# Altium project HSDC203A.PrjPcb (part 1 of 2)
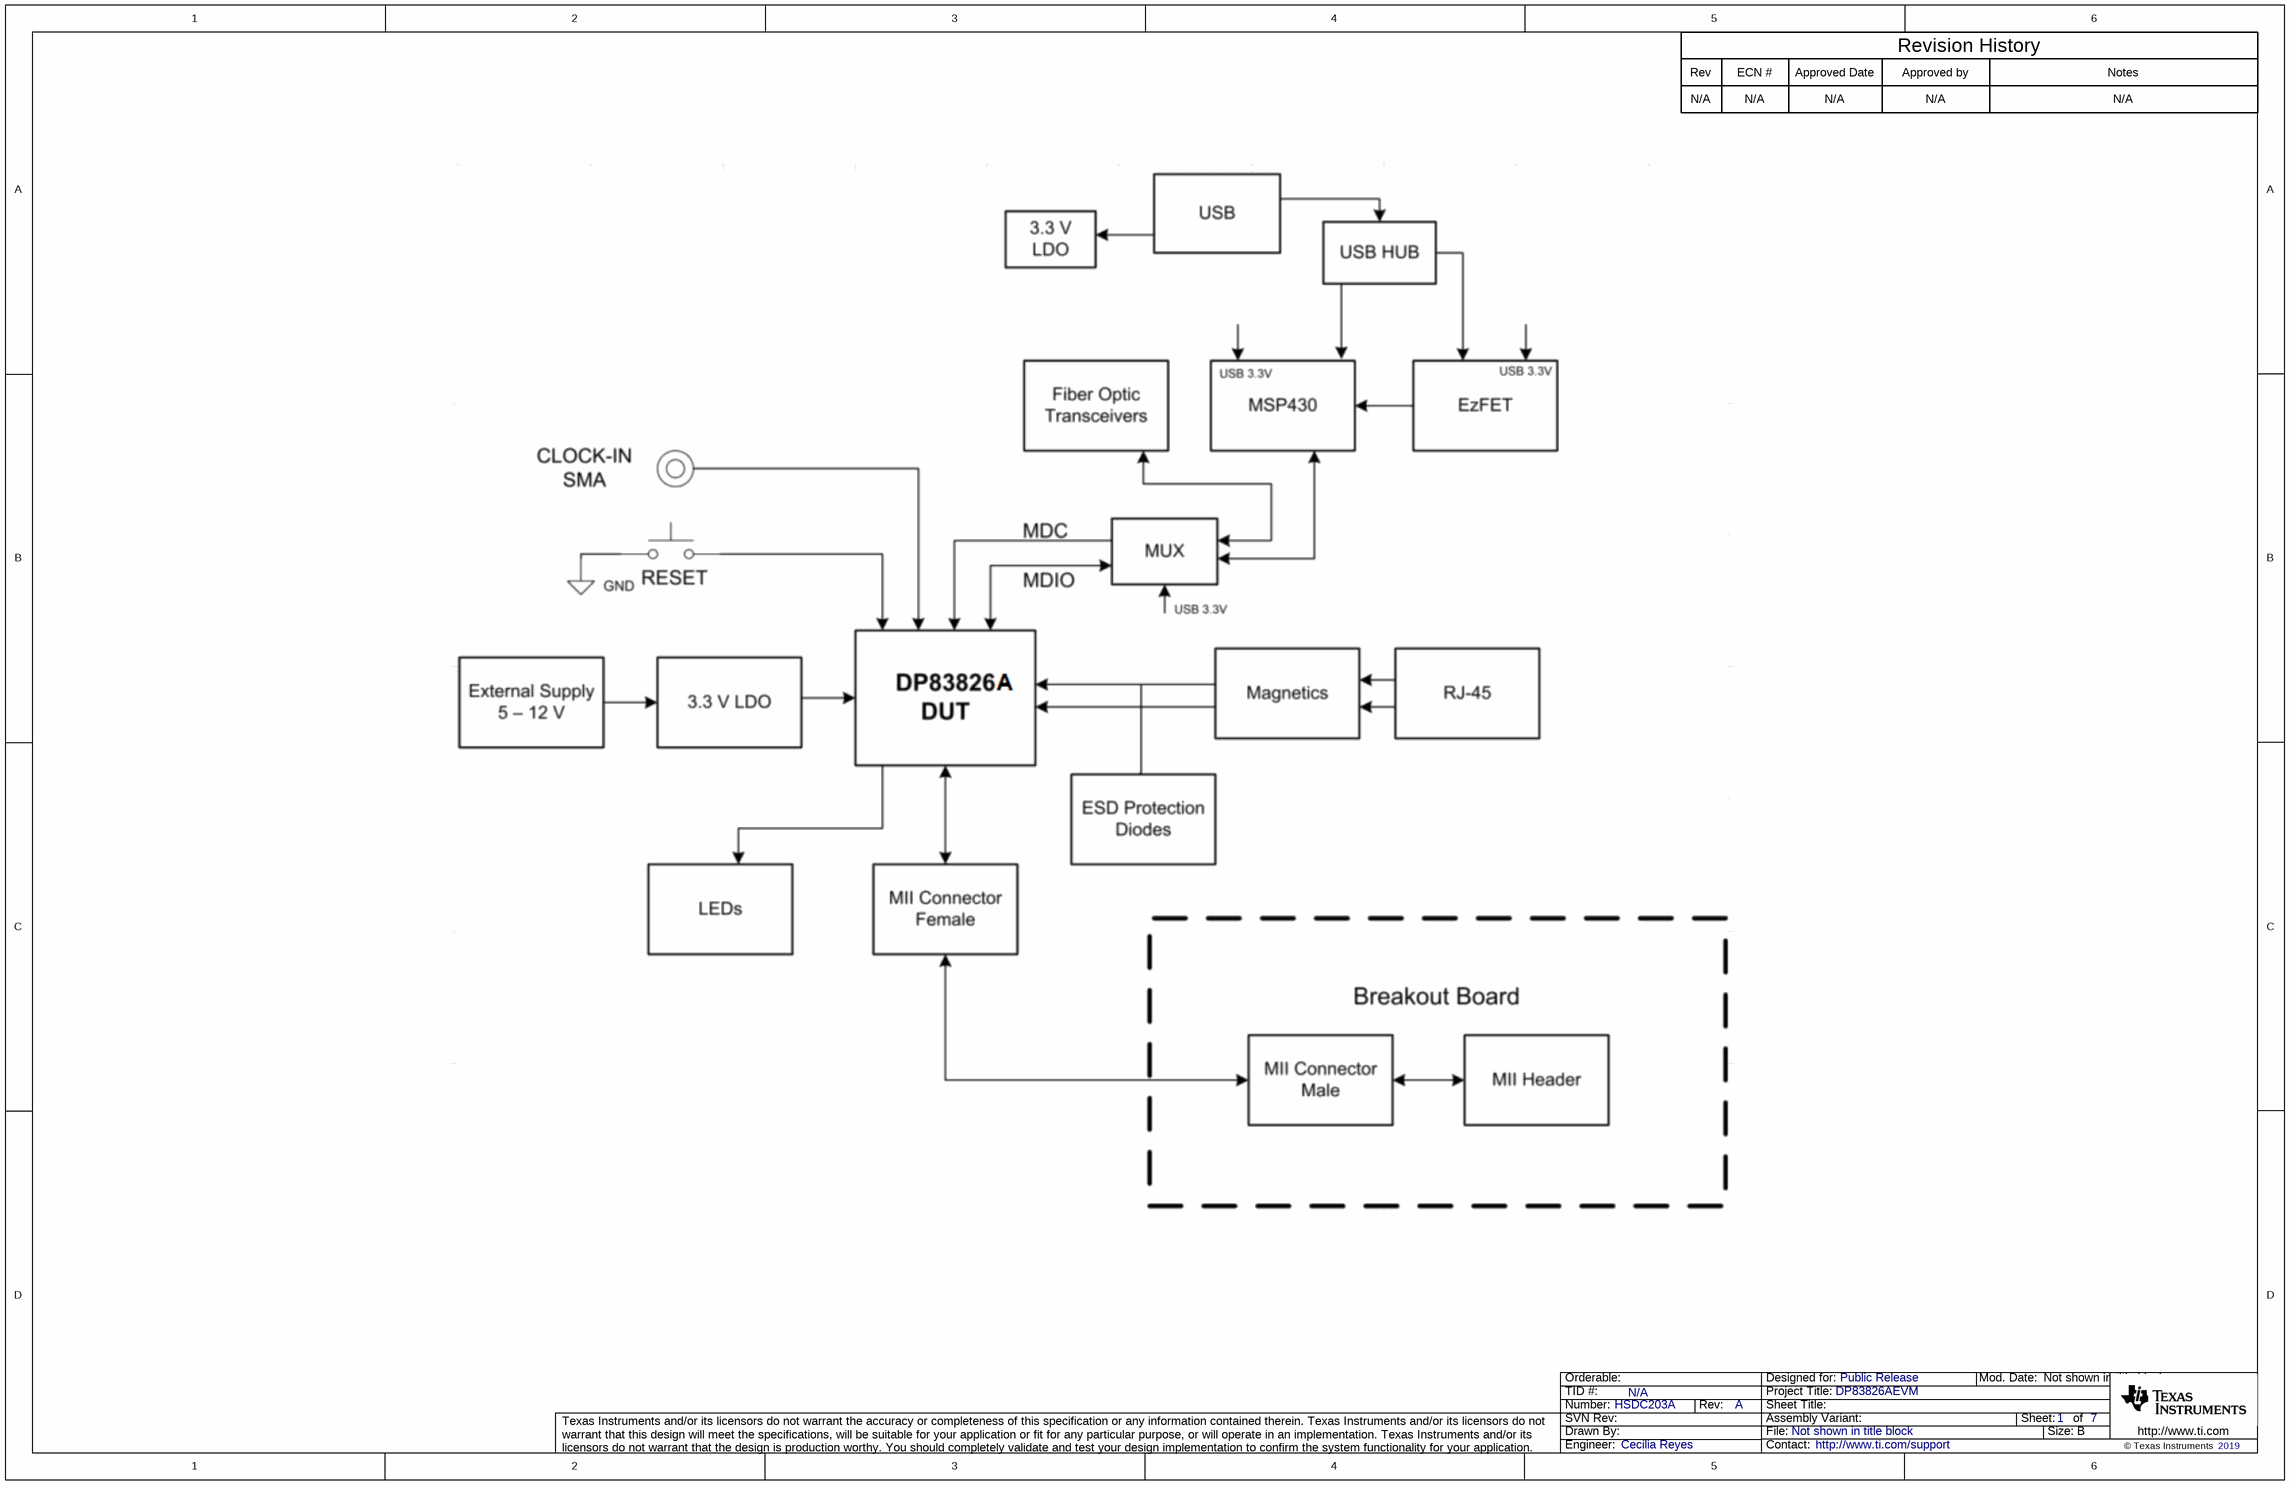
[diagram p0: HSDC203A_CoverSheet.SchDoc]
CopyrightYear: 2019; PCB_Layout: Cecilia Reyes; PCB_Rev: A; PRJ_Customer: Public Release; PRJ_Engineer: Cecilia Reyes; PRJ_Number: HSDC203A; PRJ_Title: DP83826AEVM; SCH_Rev: A; TechSupport: http://www.ti.com/support; TID: N/A
7 sheets, 303 parts. Net scope: global (net labels, ports and power ports of the same name join across sheets).
Board file: HSDC203A_02242025-3.PcbDoc
Sheets:
  HSDC203A_CoverSheet.SchDoc
  HSDC203A_Power.SchDoc
  HSDC203A_Main.SchDoc
  HSDC203A_Hub_EZFET.SchDoc
  HSDC203A_Coms.SchDoc
  HSDC203A_Breakout.SchDoc
  HSDC203A_Hardware.SchDoc

## Sheet HSDC203A_CoverSheet.SchDoc
size 431 x 279 mm; Date: Not shown in title block; ApprovedBy: Not shown in title block; CheckedBy: Not shown in title block; Author: Not shown in title block; CompanyName: Not shown in title block; Engineer: Not shown in title block; Organization: Not shown in title block; Address1: Not shown in title block; Address2: Not shown in title block; Address3: Not shown in title block; Address4: Not shown in title block; DocumentNumber: 1; Revision: Use project parameter SCH_Rev; SheetNumber: 1; SheetTotal: 7; PageSetup: Record=PageOptions¦CenterHorizontal=True¦CenterVertical=True¦PrintScale=1.00¦XCorrection=1.00¦YCorrection=1.00¦PrintKind=0¦BorderSize=5000000¦LeftOffset=0¦BottomOffset=0¦Orientation=2¦PaperLength=1000¦PaperWidth=1000¦Scale=100¦PaperSource=15¦PrintQuality=600¦MediaType=1¦DitherType=10¦PaperKind=Letter¦PrintScaleMode=1

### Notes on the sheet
- Rev
- N/A
- ECN #
- Approved Date
- Approved by
- Revision History
- Notes

## Sheet HSDC203A_Power.SchDoc: Power
size 431 x 279 mm; Date: Not shown in title block; ApprovedBy: Not shown in title block; CheckedBy: Not shown in title block; Author: Not shown in title block; CompanyName: Not shown in title block; Engineer: Not shown in title block; Organization: Not shown in title block; Address1: Not shown in title block; Address2: Not shown in title block; Address3: Not shown in title block; Address4: Not shown in title block; DocumentNumber: 2; Revision: Use project parameter SCH_Rev; SheetNumber: 2; SheetTotal: 7; PageSetup: Record=PageOptions¦CenterHorizontal=True¦CenterVertical=True¦PrintScale=1.00¦XCorrection=1.00¦YCorrection=1.00¦PrintKind=0¦BorderSize=5000000¦LeftOffset=0¦BottomOffset=0¦Orientation=2¦PaperLength=1000¦PaperWidth=1000¦Scale=100¦PaperSource=15¦PrintQuality=600¦MediaType=1¦DitherType=10¦PaperKind=Letter¦PrintScaleMode=1
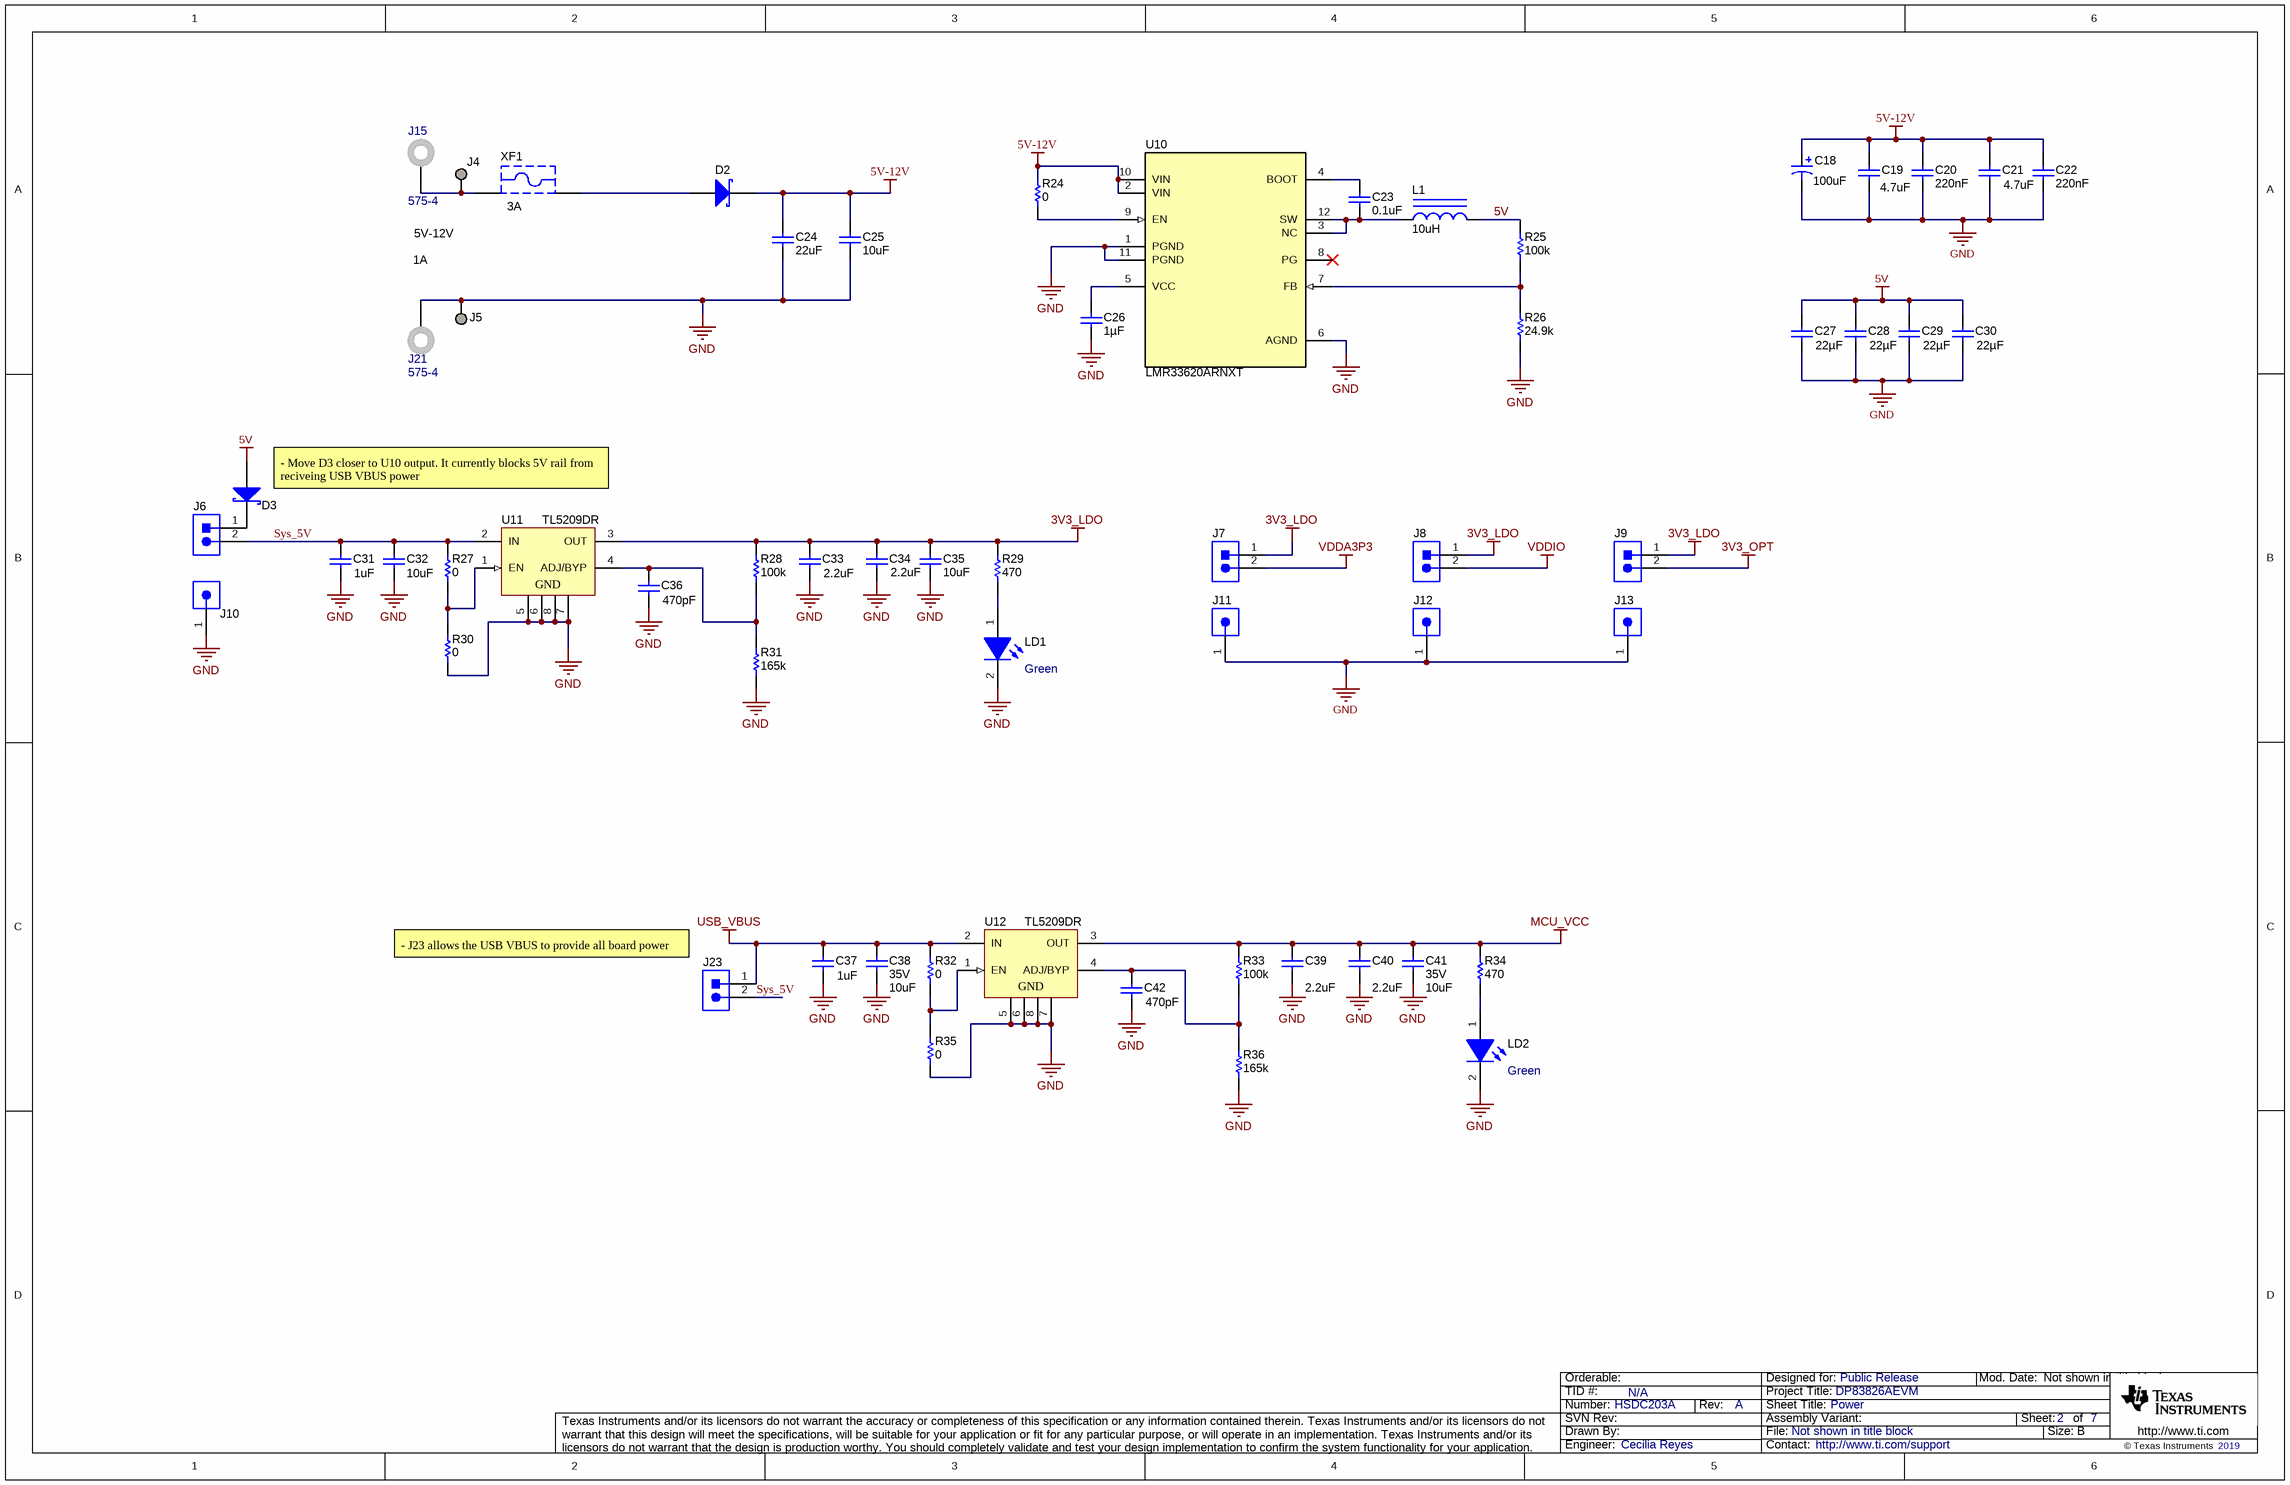
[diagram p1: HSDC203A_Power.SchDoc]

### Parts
C18  ValueDisplayed: 100uF  [CAPSMT_62_HA0]  (hidden comment: EMVE500ADA101MHA0G)
C19  ValueDisplayed: 4.7uF  [1210_280]  (hidden comment: CGA6P3X7R1H475K250AB)
C20  Cap_F: 220nF  [0603]  (hidden comment: CGA3E3X7R1H224K080AB)
C21  ValueDisplayed: 4.7uF  [1210_280]  (hidden comment: CGA6P3X7R1H475K250AB)
C22  Cap_F: 220nF  [0603]  (hidden comment: CGA3E3X7R1H224K080AB)
C23  ValueDisplayed: 0.1uF  [0402]  (hidden comment: GCM155R71H104KE02D)
C24  ValueDisplayed: 22uF  [1210_280]  (hidden comment: CGA6P1X7R1C226M250AC)
C25  ValueDisplayed: 10uF  [1210_280]  (hidden comment: CGA6P1X7R1E106M250AC)
C26  Cap_F: 1µF  [0603]  (hidden comment: CGA3E1X7R1V105K080AC)
C27  ValueDisplayed: 22µF  [1210_270]  (hidden comment: TMK325B7226KMHP)
C28  ValueDisplayed: 22µF  [1210_270]  (hidden comment: TMK325B7226KMHP)
C29  ValueDisplayed: 22µF  [1210_270]  (hidden comment: TMK325B7226KMHP)
C30  ValueDisplayed: 22µF  [1210_270]  (hidden comment: TMK325B7226KMHP)
C31  ValueDisplayed: 1uF  [0402]  (hidden comment: GRM155R6YA105ME11D)
C32  ValueDisplayed: 10uF  [0603]  (hidden comment: GRM188R6YA106MA73D)
C33  ValueDisplayed: 2.2uF  [0402]  (hidden comment: GRM155C81C225KE11D)
C34  ValueDisplayed: 2.2uF  [0402]  (hidden comment: GRM155C81C225KE11D)
C35  ValueDisplayed: 10uF  [0603]  (hidden comment: GRM188R6YA106MA73D)
C36  ValueDisplayed: 470pF  [0402]  (hidden comment: GCM155R71H471KA37D)
C37  ValueDisplayed: 1uF  [0402]  (hidden comment: GRM155R6YA105ME11D)
C38  VDC_V: 35V  ValueDisplayed: 10uF  [0603]  (hidden comment: GRM188R6YA106MA73D)
C39  ValueDisplayed: 2.2uF  [0402]  (hidden comment: GRM155C81C225KE11D)
C40  ValueDisplayed: 2.2uF  [0402]  (hidden comment: GRM155C81C225KE11D)
C41  VDC_V: 35V  ValueDisplayed: 10uF  [0603]  (hidden comment: GRM188R6YA106MA73D)
C42  ValueDisplayed: 470pF  [0402]  (hidden comment: GCM155R71H471KA37D)
D2  NRVBA160T3G  [SMA]  (value not drawn)
D3  NRVBA160T3G  [SMA]  (value not drawn)
J4  1502-2  [Keystone1502-2]  (value not drawn)
J5  1502-2  [Keystone1502-2]  (value not drawn)
J6  PEC02SAAN  [CONN_PEC02SAAN]  (value not drawn)
J7  PEC02SAAN  [CONN_PEC02SAAN]  (value not drawn)
J8  PEC02SAAN  [CONN_PEC02SAAN]  (value not drawn)
J9  PEC02SAAN  [CONN_PEC02SAAN]  (value not drawn)
J10  PEC01SAAN  [Sullins_PEC01SAAN]  (value not drawn)
J11  PEC01SAAN  [Sullins_PEC01SAAN]  (value not drawn)
J12  PEC01SAAN  [Sullins_PEC01SAAN]  (value not drawn)
J13  PEC01SAAN  [Sullins_PEC01SAAN]  (value not drawn)
J15  575-4  [Keystone_575-4]
J21  575-4  [Keystone_575-4]
J23  PEC02SAAN  [CONN_PEC02SAAN]  (value not drawn)
L1  ValueDisplayed: 10uH  [SRP5030T]  (hidden comment: SRP5030T-100M)
LD1  value Green  [QTLP630C_Green]  (hidden comment: QTLP630C4TR)
LD2  value Green  [QTLP630C_Green]  (hidden comment: QTLP630C4TR)
R24  ValueDisplayed: 0  [0603]  (hidden comment: RMCF0603ZT0R00)
R25  ValueDisplayed: 100k  [0603]  (hidden comment: CRCW0603100KFKEA)
R26  ValueDisplayed: 24.9k  [0603]  (hidden comment: CRCW060324K9FKEA)
R27  ValueDisplayed: 0  [0603]  (hidden comment: ERJ-3GEY0R00V)
R28  ValueDisplayed: 100k  [0402]  (hidden comment: CRCW0402100KDHEDP)
R29  ValueDisplayed: 470  [0402]  (hidden comment: CRCW0402470RJNED)
R30  ValueDisplayed: 0  [0603]  (hidden comment: ERJ-3GEY0R00V)
R31  ValueDisplayed: 165k  [0402]  (hidden comment: CRCW0402165KFKED)
R32  ValueDisplayed: 0  [0603]  (hidden comment: ERJ-3GEY0R00V)
R33  ValueDisplayed: 100k  [0402]  (hidden comment: CRCW0402100KDHEDP)
R34  ValueDisplayed: 470  [0402]  (hidden comment: CRCW0402470RJNED)
R35  ValueDisplayed: 0  [0603]  (hidden comment: ERJ-3GEY0R00V)
R36  ValueDisplayed: 165k  [0402]  (hidden comment: CRCW0402165KFKED)
U10  LMR33620ARNXT  [RNX0012B]
U11  TL5209DR  [D0008A_N]
U12  TL5209DR  [D0008A_N]
XF1  0031.7701.11  [Schurter_0031-7701-11]  (value not drawn)

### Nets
3V3_LDO: C33.1 C34.1 C35.1 J7.1 J8.1 J9.1 R28.2 R29.2 U11.3(OUT)
3V3_OPT: J9.2
5V: C27.1 C28.1 C29.1 C30.1 D3.2(A) L1.2 R25.2
5V-12V: C18.1(+) C19.1 C20.1 C21.1 C22.1 C24.1 C25.1 D2.1(K) R24.2 U10.2(VIN) U10.10(VIN)
GND: C18.2(-) C19.2 C20.2 C21.2 C22.2 C24.2 C25.2 C26.2 C27.2 C28.2 C29.2 C30.2 C31.2 C32.2 C33.2 C34.2 C35.2 C36.2 C37.2 C38.2 C39.2 C40.2 C41.2 C42.2 J5.1 J10.1 J11.1 J12.1 J13.1 J21.1 LD1.2(K) LD2.2(K) R26.1 R30.1 R31.1 R35.1 R36.1 U10.1(PGND) U10.6(AGND) U10.11(PGND) U11.5(GND) U11.6(GND) U11.7(GND) U11.8(GND) U12.5(GND) U12.6(GND) U12.7(GND) U12.8(GND)
MCU_VCC: C39.1 C40.1 C41.1 R33.2 R34.2 U12.3(OUT)
USB_VBUS: C37.1 C38.1 J23.1 R32.2 U12.2(IN)
VDDA3P3: J7.2
VDDIO: J8.2
Sys_5V: C31.1 C32.1 J6.2 J23.2 R27.2 U11.2(IN)
NetC23_1: C23.1 U10.4(BOOT)
NetC23_2: C23.2 L1.1 U10.3(NC) U10.12(SW)
NetC26_1: C26.1 U10.5(VCC)
NetC36_1: C36.1 R28.1 R31.2 U11.4(ADJ/BYP)
NetC42_1: C42.1 R33.1 R36.2 U12.4(ADJ/BYP)
NetD2_2: D2.2(A) XF1.1
NetD3_1: D3.1(K) J6.1
NetJ4_1: J4.1 J15.1 XF1.2
NetLD1_1: LD1.1(A) R29.1
NetLD2_1: LD2.1(A) R34.1
NetR24_1: R24.1 U10.9(EN)
NetR25_1: R25.1 R26.2 U10.7(FB)
NetR27_1: R27.1 R30.2 U11.1(EN)
NetR32_1: R32.1 R35.2 U12.1(EN)

Not connected (* = marked no-connect by the designer): U10 8(PG)*

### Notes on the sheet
- 5V-12V
- (near XF1) 3A
- 1A
- (near D3) - Move D3 closer to U10 output. It currently blocks 5V rail from reciveing USB VBUS power
- (near J23) - J23 allows the USB VBUS to provide all board power

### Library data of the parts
C18 = CMP-0011279-3: CAP, AL, 100 uF, 50 V, +/- 20%, SMD; Manufacturer: Chemi-Con; TaMin_C: -40°C; Polarized: Y; SizeAreaWB_mm2: 106.09; Value1: Unknown; U/M: EA; Value: 100uF; TaMax_C: 105°C; SizeZ_mm: 10; SizeX_mm: 8.3; Cap_Case: HA0; Value2: 50V; SizeArea_mm2: 68.89; CompType: Capacitor; Cap_F: 100µF; IRMS_A: 230mA; AEC Category: Q200
C19 C21 = CMP-0009162-2: CAP, CERM, 4.7 uF, 50 V, +/- 10%, X7R, AEC-Q200 Grade 1, 1210; Manufacturer: TDK; TaMin_C: -55°C; ESR_ohm: 3.166m; Polarized: N; SizeAreaWB_mm2: 14.7; Value1: 0.003166 ohm; U/M: EA; Value: 4.7uF; TaMax_C: 125°C; SizeZ_mm: 2.8; SizeX_mm: 3.2; SizeY_mm: 2.5; Value2: 50V; SizeArea_mm2: 8; AEC Qualified: Y; Cap_F: 4.7µF; IRMS_A: 4.13311A; AEC Grade: 1; AEC Category: Q200
C20 C22 = CMP-0007094-5: CAP, CERM, 0.22 uF, 50 V, +/- 10%, X7R, AEC-Q200 Grade 1, 0603; Manufacturer: TDK; TaMin_C: -55°C; ESR_ohm: 0.021699; Polarized: N; SizeAreaWB_mm2: 4.68; Value1: 0.021699 ohm; U/M: EA; Value: 0.22uF; TaMax_C: 125°C; SizeZ_mm: 1; SizeX_mm: 1.6; SizeY_mm: 0.8; Value2: 50V; SizeArea_mm2: 1.28; AEC Qualified: Y; IRMS_A: 1.12496A; AEC Category: Q200
C23 = CMP-0006356-2: CAP, CERM, 0.1 uF, 50 V, +/- 10%, X7R, AEC-Q200 Grade 1, 0402; Manufacturer: MuRata; TaMin_C: -55°C; Polarized: N; SizeAreaWB_mm2: 3; Value1: Unknown; U/M: EA; Value: 0.1uF; TaMax_C: 125°C; SizeZ_mm: 0.6; SizeX_mm: 1; SizeY_mm: 0.5; Value2: 50V; AEC Qualified: Y; Cap_F: 100nF; AEC Category: Q200
C24 = CMP-0009154-2: CAP, CERM, 22 uF, 16 V, +/- 20%, X7R, AEC-Q200 Grade 1, 1210; Manufacturer: TDK; Polarized: N; Value: 22uF; U/M: EA; Cap_F: 22µF; ESR_ohm: 2.582m; Value1: 0.002582 ohm; VDC_V: 16V; IRMS_A: 4.57562A; TaMin_C: -55°C; TaMax_C: 125°C; AEC Category: Q200; AEC Qualified: Y; AEC Grade: 1; SizeArea_mm2: 8; SizeAreaWB_mm2: 14.7; SizeX_mm: 3.2; SizeY_mm: 2.5; SizeZ_mm: 2.8
C25 = CMP-0009155-2: CAP, CERM, 10 uF, 25 V, +/- 20%, X7R, AEC-Q200 Grade 1, 1210; Manufacturer: TDK; Polarized: N; Value: 10uF; U/M: EA; Cap_F: 10µF; Value1: Unknown; VDC_V: 25V; TaMin_C: -55°C; TaMax_C: 125°C; Cap_Case: 1210; AEC Category: Q200; AEC Qualified: Y; AEC Grade: 1; SizeArea_mm2: 8; SizeAreaWB_mm2: 14.7; SizeX_mm: 3.2; SizeY_mm: 2.5; SizeZ_mm: 2.8
C26 = CMP-0007067-4: CAP, CERM, 1 uF, 35 V, +/- 10%, X7R, AEC-Q200 Grade 1, 0603; Manufacturer: TDK; TaMin_C: -55°C; ESR_ohm: 5.522m; Polarized: N; SizeAreaWB_mm2: 4.68; Value1: 0.005522 ohm; U/M: EA; Value: 1uF; TaMax_C: 125°C; SizeZ_mm: 1; SizeX_mm: 1.6; SizeY_mm: 0.8; Value2: 35V; SizeArea_mm2: 1.28; AEC Qualified: Y; IRMS_A: 2.21617A; AEC Category: Q200
C27-C30 = CMP-0080552-1: CAP, CERM, 22 µF, 25 V,+/- 10%, X7R, AEC-Q200 Grade 1, 1210; Manufacturer: Taiyo Yuden; TaMin_C: -55°C; Polarized: N; SizeAreaWB_mm2: 14.7; U/M: EA; Value: 22uF; TaMax_C: 125°C; SizeZ_mm: 2.7; SizeX_mm: 3.2; SizeY_mm: 2.5; Cap_Case: 1210; Value2: 25V; SizeArea_mm2: 8; AEC Qualified: Y; AEC Grade: 1; AEC Category: Q200
C31 C37 = CMP-0006620-2: CAP, CERM, 1 uF, 35 V, +/- 20%, X5R, 0402; Manufacturer: MuRata; TaMin_C: -55°C; Polarized: N; SizeAreaWB_mm2: 3; Value1: Unknown; U/M: EA; Value: 1uF; TaMax_C: 85°C; SizeZ_mm: 0.6; SizeX_mm: 1; SizeY_mm: 0.5; Value2: 35V; Cap_F: 1µF; AEC Category: Q200
C32 C35 = CMP-0007355-6: CAP, CERM, 10 uF, 35 V, +/- 20%, X5R, 0603; Manufacturer: Murata; TaMin_C: -55°C; Polarized: N; SizeAreaWB_mm2: 4.68; Value1: Unknown; U/M: EA; Value: 10uF; TaMax_C: 85°C; SizeZ_mm: 1; SizeX_mm: 1.6; SizeY_mm: 0.8; Value2: 35V; SizeArea_mm2: 1.28; Cap_F: 10µF; AEC Category: Q200
C33 C34 C39 C40 = CMP-0006526-2: CAP, CERM, 2.2 uF, 16 V, +/- 10%, X6S, 0402; Manufacturer: MuRata; TaMin_C: -55°C; Polarized: N; SizeAreaWB_mm2: 3; Value1: Unknown; U/M: EA; Value: 2.2uF; TaMax_C: 105°C; SizeZ_mm: 0.6; SizeX_mm: 1; SizeY_mm: 0.5; Value2: 16V; Cap_F: 2.2µF; AEC Category: Q200
C36 C42 = CMP-0006360-2: CAP, CERM, 470 pF, 50 V, +/- 10%, X7R, AEC-Q200 Grade 1, 0402; Manufacturer: MuRata; TaMin_C: -55°C; Polarized: N; SizeAreaWB_mm2: 3; Value1: Unknown; U/M: EA; Value: 470pF; TaMax_C: 125°C; SizeZ_mm: 0.6; SizeX_mm: 1; SizeY_mm: 0.5; Value2: 50V; AEC Qualified: Y; AEC Category: Q200
C38 C41 = CMP-0007355-6: CAP, CERM, 10 uF, 35 V, +/- 20%, X5R, 0603; Manufacturer: Murata; TaMin_C: -55°C; Polarized: N; SizeAreaWB_mm2: 4.68; Value1: Unknown; U/M: EA; Value: 10uF; TaMax_C: 85°C; SizeZ_mm: 1; SizeX_mm: 1.6; SizeY_mm: 0.8; SizeArea_mm2: 1.28; Cap_F: 10µF; AEC Category: Q200
D2 D3 = CMP-0028762-2: Diode, Schottky, 60 V, 1 A, AEC-Q101, SMA; Manufacturer: ON Semiconductor; Vf_V: 510mV; Value: 60V; Value1: 1A; Value2: 0.51V; TJmax_C: 150°C; AEC Category: Q101; AEC Qualified: Y; Green_Lifecycle: Active; Green_REACh: Passed; SizeArea_mm2: 16.3228; SizeAreaWB_mm2: 37.3428; SizeX_mm: 5.59; SizeY_mm: 2.92; SizeZ_mm: 2.87
J4 J5 = CMP-0055113-1: Terminal, Turret, TH, Double; Manufacturer: Keystone; CompType: Turret Terminal; CNHeader: FALSE; Green_Lifecycle: Active; Green_REACh: Passed
J6-J9 J23 = CMP-0002337-1: Header, 100mil, 2x1, Tin, TH; Manufacturer: Sullins Connector Solutions; CNHeader: TRUE; Current_A: 3A; Green_Lifecycle: Not Set; Shrouded: N; Gender: Male; Green_REACh: Incomplete; Voltage_V: 1.8kV; Row_Count: 1; Pitch_mm: 2.54; CT: FALSE; Cert_UL: Y
J10-J13 = CMP-0054706-1: Header, 1x1, Tin, TH; Manufacturer: Sullins Connector Solutions; CNHeader: FALSE; Current_A: 3A; Green_Lifecycle: Not Set; Shrouded: N; Gender: Male; Green_REACh: Incomplete; Voltage_V: 1.8kV; Row_Count: 1; Pitch_mm: 2.54; Cert_UL: Y
J15 J21 = CMP-0055165-2: Standard Banana Jack, Uninsulated, 5.5mm; Manufacturer: Keystone; CT: TRUE; Green_REACh: Passed; CNHeader: FALSE; Green_Lifecycle: Active
L1 = CMP-0056947-1: Inductor, Shielded, Ferrite, 10 uH, 2.75 A, 0.128 ohm, SMD; Manufacturer: Bourns; Isat: 3.5A @ 20% inductance drop; Irms: 2.75A @ 40C rise; Green_Lifecycle: Active; SizeAreaWB_mm2: 59.2; DCR_ohm: 0.128; Green_REACh: Passed; Value: 10uH; Imax_A: 2.75A; SizeZ_mm: 3; SizeX_mm: 6; SizeY_mm: 5.4; SizeArea_mm2: 32.4; Ind_H: 10µH; AEC Category: Q200
LD1 LD2 = CMP-0002917-2: LED, Green, SMD; Manufacturer: Everlight; Vf_V: 2.1V; Io_A: 20mA; Vr_V: 5V; Tjmax_C: 85°C; Value1: W; Angle: 140
R24 = CMP-0023343-3: RES, 0, 1%, 0.1 W, AEC-Q200 Grade 0, 0603; Manufacturer: Stackpole Electronics Inc; Power_W: 100mW; TempCo: ppm/C; U/M: EA; Value: 0; SizeX_mm: 1.6; SizeY_mm: 0.8; SizeZ_mm: 1; Value2: 0.1W; SizeArea_mm2: 1.28; AEC Qualified: Y; AEC Category: Q200
R25 = CMP-0021990-4: RES, 100 k, 1%, 0.1 W, AEC-Q200 Grade 0, 0603; Manufacturer: Vishay-Dale; Power_W: 100mW; TempCo: 100 ppm/C; Value: 100k; EIA_Code: E96; SizeX_mm: 1.6; SizeY_mm: 0.8; SizeZ_mm: 1; Value2: 0.1W; SizeArea_mm2: 1.28; AEC Qualified: Y; VDC_V: 75V; AEC Category: Q200; AEC Grade: 0
R26 = CMP-0022237-4: RES, 24.9 k, 1%, 0.1 W, AEC-Q200 Grade 0, 0603; Manufacturer: Vishay-Dale; Power_W: 100mW; TempCo: 100 ppm/C; Value_Code: 24k9; Value: 24.9k; EIA_Code: E96; SizeX_mm: 1.6; SizeY_mm: 0.8; SizeZ_mm: 1; Value2: 0.1W; SizeArea_mm2: 1.28; AEC Qualified: Y; VDC_V: 75V; AEC Category: Q200; AEC Grade: 0
R27 R30 R32 R35 = CMP-0025874-4: RES, 0, 5%, 0.1 W, AEC-Q200 Grade 0, 0603; Manufacturer: Panasonic; Power_W: 100mW; TempCo: 600 ppm/C; Value_Code: 0000; Value: 0; EIA_Code: E24; SizeX_mm: 1.6; SizeY_mm: 0.8; SizeZ_mm: 1; Value2: 0.1W; SizeArea_mm2: 1.28; AEC Qualified: Y; VDC_V: 50V; AEC Category: Q200; SizeAreaWB_mm2: 4.68
R28 R33 = CMP-0026768-2: RES, 100 k, 0.5%, 0.063 W, AEC-Q200 Grade 0, 0402; Manufacturer: Vishay-Dale; Power_W: 63mW; TempCo: 50 ppm/C; Value: 100k; EIA_Code: E192; SizeX_mm: 1; SizeY_mm: 0.5; SizeZ_mm: 0.6; Value2: 0.063W; AEC Qualified: Y; VDC_V: 50V; AEC Category: Q200; AEC Grade: 0
R29 R34 = CMP-0026934-3: RES, 470, 5%, 0.063 W, AEC-Q200 Grade 0, 0402; Manufacturer: Vishay-Dale; Power_W: 63mW; TempCo: 200 ppm/C; Value_Code: 470R; Value: 470; EIA_Code: E24; SizeX_mm: 1; SizeY_mm: 0.5; SizeZ_mm: 0.6; Value2: 0.063W; AEC Qualified: Y; VDC_V: 50V; AEC Category: Q200; AEC Grade: 0
R31 R36 = CMP-0026036-3: RES, 165 k, 1%, 0.063 W, AEC-Q200 Grade 0, 0402; Manufacturer: Vishay-Dale; Power_W: 63mW; TempCo: 100 ppm/C; Value: 165k; EIA_Code: E96; SizeX_mm: 1; SizeY_mm: 0.5; SizeZ_mm: 0.6; Value2: 0.063W; AEC Qualified: Y; VDC_V: 50V; AEC Category: Q200; AEC Grade: 0
U10 = CMP-0081171-4: 3.8-V to 36-V 2-A Synchronous Step-Down Voltage Regulator, RNX0012B (VQFN-HR-12); Manufacturer: Texas Instruments; Alternate PartNumber: LMR33620ARNXR; AEC Qualified: N; SizeZ_mm: 0.9; SizeAreaWB_mm2: 12.0; AEC Category: Q200; SizeX_mm: 2.0; SizeY_mm: 3.0; SizeArea_mm2: 6.0; Rating: Catalog; CompType: IC
U11 U12 = CMP-0036447-1: Single Output Low Noise LDO, 500 mA, Adjustable 1.3 to 6.5 V Output, 2.5 to 16 V Input, 8-pin SOIC (D), -40 to 125 degC, Green (RoHS & no Sb/Br); Manufacturer: Texas Instruments; Iq(Typ)(mA): 8; Accuracy(%): 2; Vdo(Typ)(mV): 500; Iout(Max)(A): 0.5; Vin(Max)(V): 16; Vout Adj(Min)(V): 2.5; Vout Adj(Max)(V): 6.5; SubFamily: Single Channel LDO; Rating: Catalog
XF1 = CMP-0077258-1: FUSE HLDR CARTRIDGE 125V 5A SMD; Manufacturer: Schurter; CompType: Fuse Holder

## Sheet HSDC203A_Main.SchDoc: DP83826
size 431 x 279 mm; Date: Not shown in title block; ApprovedBy: Not shown in title block; CheckedBy: Not shown in title block; Author: Not shown in title block; CompanyName: Not shown in title block; Engineer: Not shown in title block; Organization: Not shown in title block; Address1: Not shown in title block; Address2: Not shown in title block; Address3: Not shown in title block; Address4: Not shown in title block; DocumentNumber: 3; Revision: Use project parameter SCH_Rev; SheetNumber: 3; SheetTotal: 7; PageSetup: Record=PageOptions¦CenterHorizontal=True¦CenterVertical=True¦PrintScale=1.00¦XCorrection=1.00¦YCorrection=1.00¦PrintKind=0¦BorderSize=5000000¦LeftOffset=0¦BottomOffset=0¦Orientation=2¦PaperLength=1000¦PaperWidth=1000¦Scale=100¦PaperSource=15¦PrintQuality=600¦MediaType=1¦DitherType=10¦PaperKind=Letter¦PrintScaleMode=1
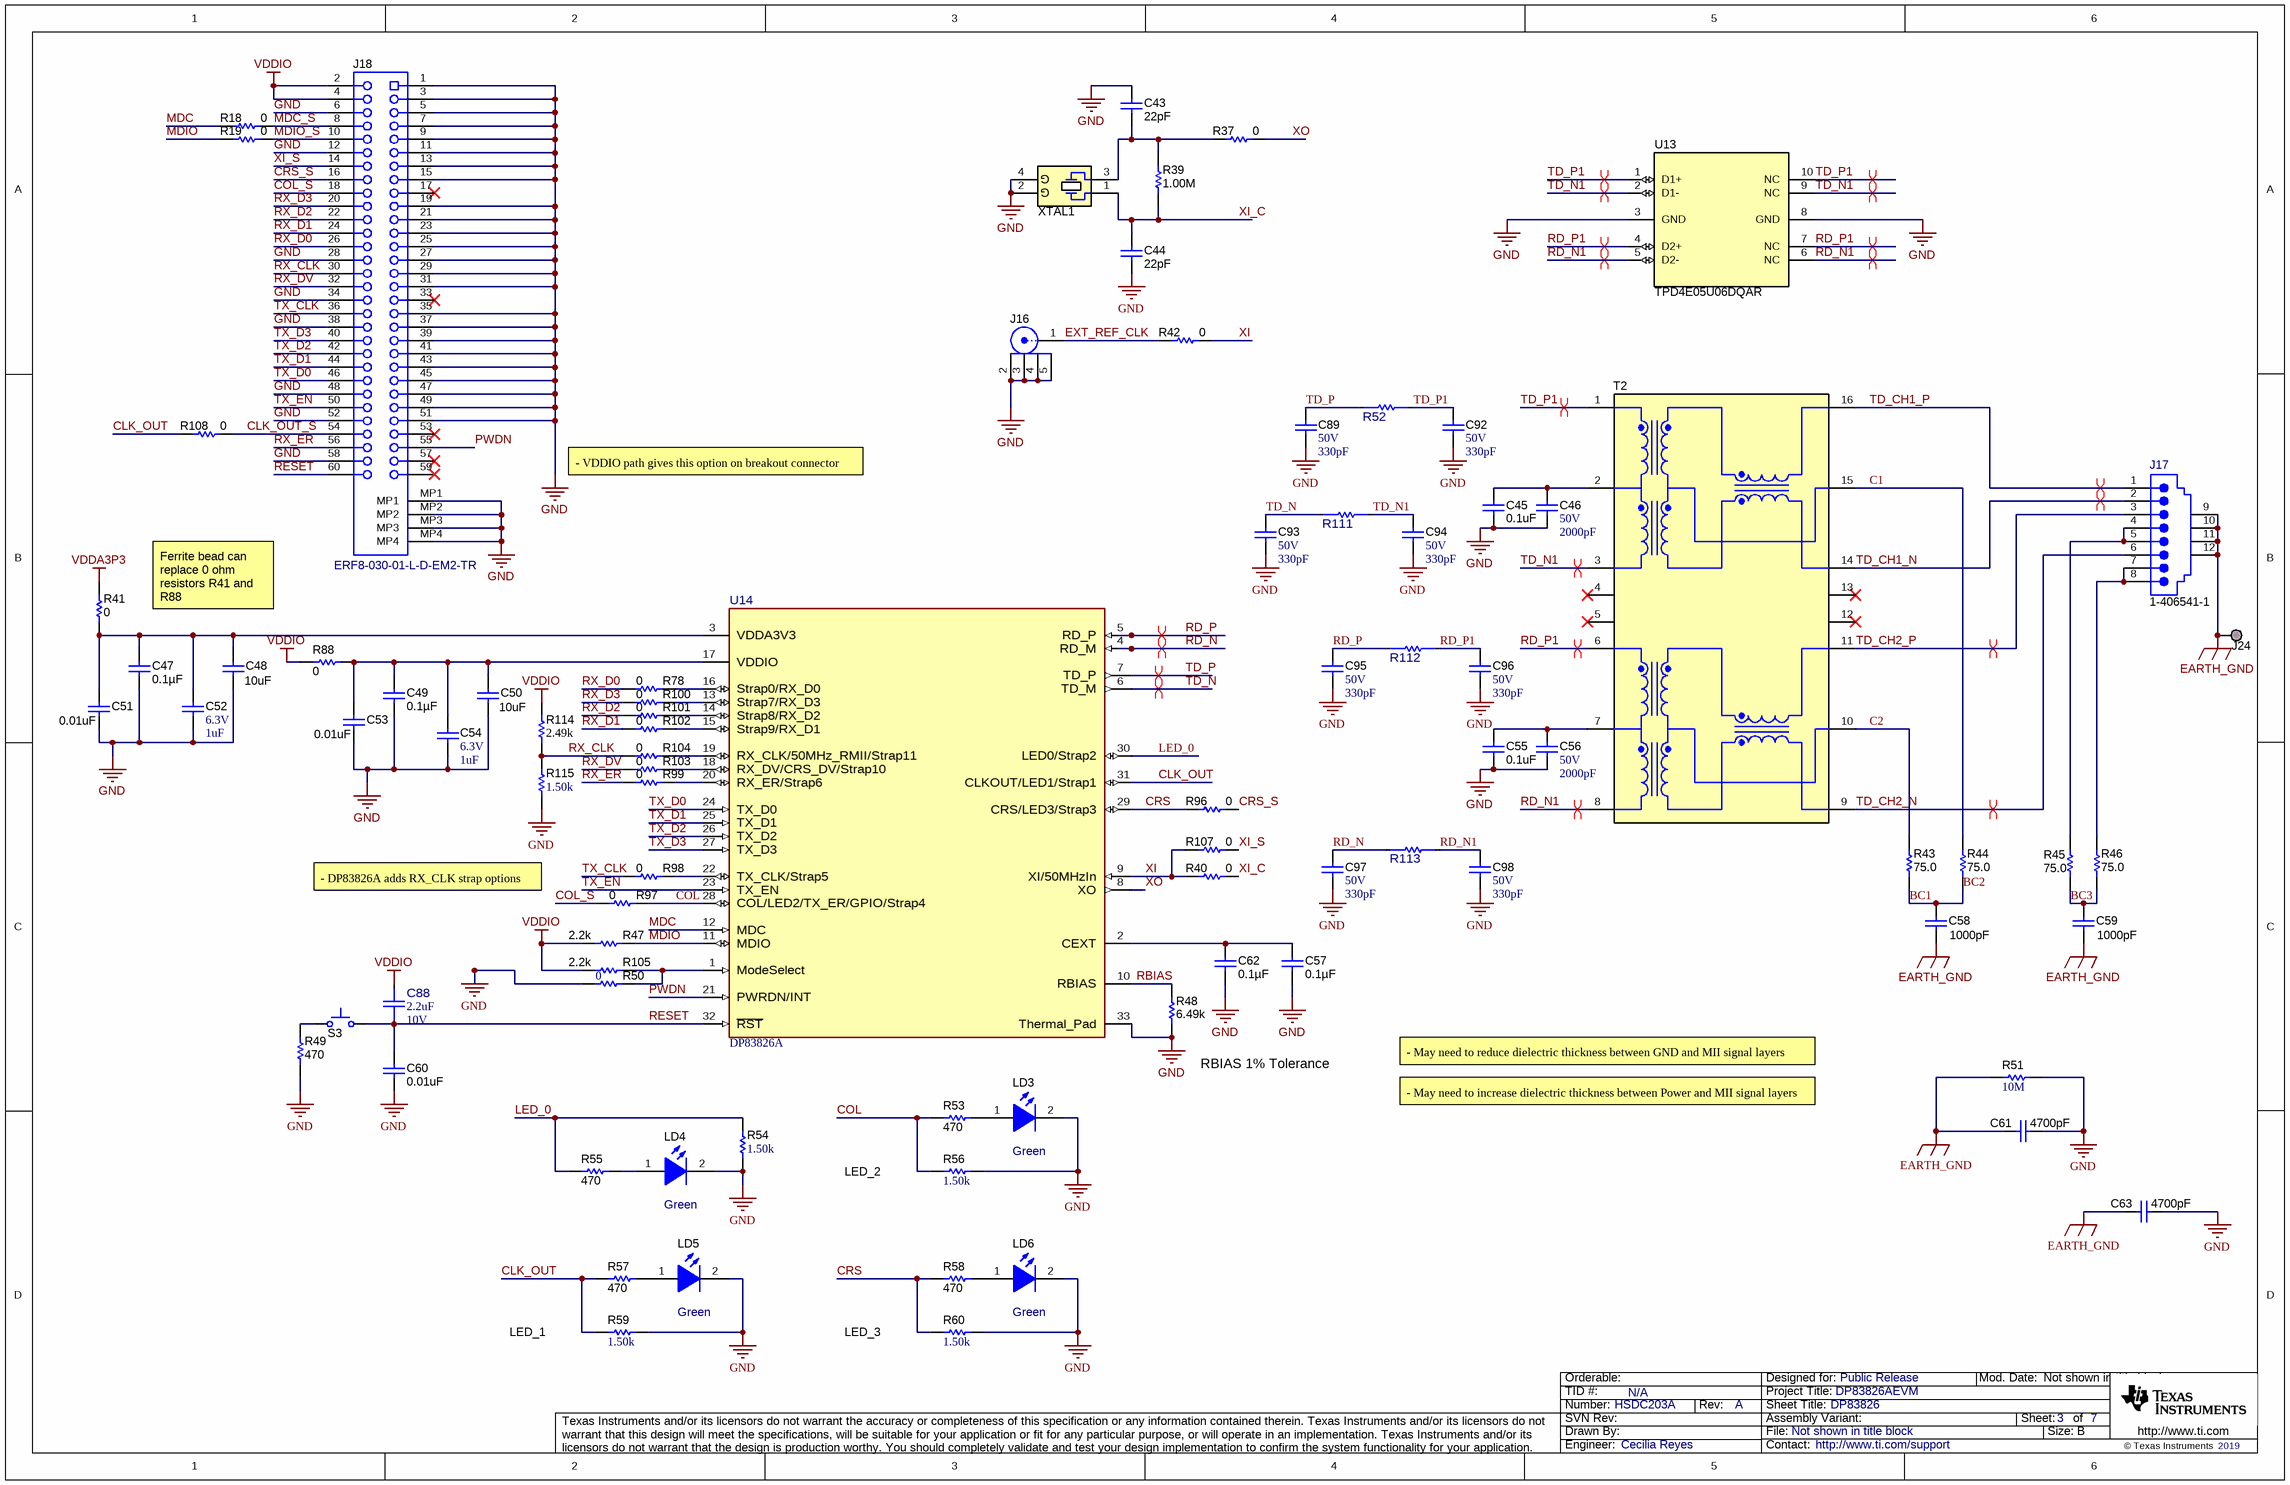
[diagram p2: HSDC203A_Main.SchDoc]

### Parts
C43  ValueDisplayed: 22pF  [0603]  (hidden comment: CGA3E2C0G1H220J080AA)
C44  ValueDisplayed: 22pF  [0603]  (hidden comment: CGA3E2C0G1H220J080AA)
C45  ValueDisplayed: 0.1uF  [0603]  (hidden comment: C0603C104K8RACTU)
C46  VDC_V: 50V  ValueDisplayed: 2000pF  [0603]  (hidden comment: GRM1885C1H202JA01D)
C47  ValueDisplayed: 0.1µF  [0402]  (hidden comment: C0402C104K8RACTU)
C48  ValueDisplayed: 10uF  [0402]  (hidden comment: CL05A106MQ5NUNC)
C49  ValueDisplayed: 0.1µF  [0402]  (hidden comment: C0402C104K8RACTU)
C50  ValueDisplayed: 10uF  [0402]  (hidden comment: CL05A106MQ5NUNC)
C51  ValueDisplayed: 0.01uF  [0402]  (hidden comment: 885012205031)
C52  VDC_V: 6.3V  ValueDisplayed: 1uF  [0402]  (hidden comment: GRM155R70J105KA12D)
C53  ValueDisplayed: 0.01uF  [0402]  (hidden comment: 885012205031)
C54  VDC_V: 6.3V  ValueDisplayed: 1uF  [0402]  (hidden comment: GRM155R70J105KA12D)
C55  ValueDisplayed: 0.1uF  [0603]  (hidden comment: C0603C104K8RACTU)
C56  VDC_V: 50V  ValueDisplayed: 2000pF  [0603]  (hidden comment: GRM1885C1H202JA01D)
C57  ValueDisplayed: 0.1µF  [0402]  (hidden comment: C0402C104K8RACTU)
C58  ValueDisplayed: 1000pF  [1206_180]  (hidden comment: C1206C102KGRACAUTO)
C59  ValueDisplayed: 1000pF  [1206_180]  (hidden comment: C1206C102KGRACAUTO)
C60  ValueDisplayed: 0.01uF  [0402]  (hidden comment: 885012205031)
C61  ValueDisplayed: 4700pF  [1812_254]  (hidden comment: 1812GC472KAT1A)
C62  ValueDisplayed: 0.1µF  [0402]  (hidden comment: C0402C104K8RACTU)
C63  ValueDisplayed: 4700pF  [1812_254]  (hidden comment: 1812GC472KAT1A)
C88  ValueDisplayed: 2.2uF  VDC_V: 10V  [FP-GRM155Z71A225KE01D_0402-MFG]  (hidden comment: GRM155Z71A225KE01D)
C89  VDC_V: 50V  ValueDisplayed: 330pF  [0201_033]  (hidden comment: CGA1A2X7R1H331K030BA)
C92  VDC_V: 50V  ValueDisplayed: 330pF  [0201_033]  (hidden comment: CGA1A2X7R1H331K030BA)
C93  VDC_V: 50V  ValueDisplayed: 330pF  [0201_033]  (hidden comment: CGA1A2X7R1H331K030BA)
C94  VDC_V: 50V  ValueDisplayed: 330pF  [0201_033]  (hidden comment: CGA1A2X7R1H331K030BA)
C95  VDC_V: 50V  ValueDisplayed: 330pF  [0201_033]  (hidden comment: CGA1A2X7R1H331K030BA)
C96  VDC_V: 50V  ValueDisplayed: 330pF  [0201_033]  (hidden comment: CGA1A2X7R1H331K030BA)
C97  VDC_V: 50V  ValueDisplayed: 330pF  [0201_033]  (hidden comment: CGA1A2X7R1H331K030BA)
C98  VDC_V: 50V  ValueDisplayed: 330pF  [0201_033]  (hidden comment: CGA1A2X7R1H331K030BA)
J16  5-1814832-1  [TE_5-1814832-1]  (value not drawn)
J17  1-406541-1  [TEC_1-406541-1]
J18  ERF8-030-01-L-D-EM2-TR  [Samtec_ERF8-030-01-x-D-EM2]
J24  1502-2  [Keystone1502-2]  (value not drawn)
LD3  value Green  [QTLP630C_Green]  (hidden comment: QTLP630C4TR)
LD4  value Green  [QTLP630C_Green]  (hidden comment: QTLP630C4TR)
LD5  value Green  [QTLP630C_Green]  (hidden comment: QTLP630C4TR)
LD6  value Green  [QTLP630C_Green]  (hidden comment: QTLP630C4TR)
R18  ValueDisplayed: 0  [0201]  (hidden comment: CRCW02010000Z0ED)
R19  ValueDisplayed: 0  [0201]  (hidden comment: CRCW02010000Z0ED)
R37  ValueDisplayed: 0  [0201]  (hidden comment: CRCW02010000Z0ED)
R39  ValueDisplayed: 1.00M  [0402]  (hidden comment: RC0402FR-071ML)
R40  ValueDisplayed: 0  [0201]  (hidden comment: CRCW02010000Z0ED)
R41  ValueDisplayed: 0  [0603]  (hidden comment: CRCW06030000Z0EA)
R42  ValueDisplayed: 0  [0201]  (hidden comment: CRCW02010000Z0ED)
R43  ValueDisplayed: 75.0  [0805_HV]  (hidden comment: CRCW080575R0FKEA)
R44  ValueDisplayed: 75.0  [0805_HV]  (hidden comment: CRCW080575R0FKEA)
R45  ValueDisplayed: 75.0  [0805_HV]  (hidden comment: CRCW080575R0FKEA)
R46  ValueDisplayed: 75.0  [0805_HV]  (hidden comment: CRCW080575R0FKEA)
R47  ValueDisplayed: 2.2k  [0402]  (hidden comment: CRCW04022K20JNED)
R48  ValueDisplayed: 6.49k  [0402]  (hidden comment: CRCW04026K49FKED)
R49  ValueDisplayed: 470  [0201]  (hidden comment: RC0201JR-07470RL)
R50  ValueDisplayed: 0  [0201]  (hidden comment: ERJ-1GN0R00C)
R51  ValueDisplayed: 10M  [2010]  (hidden comment: HVC2010-10MJT3)
R52  5113  [FP-5113_0402-MFG]  (value not drawn)
R53  ValueDisplayed: 470  [0402]  (hidden comment: CRCW0402470RJNED)
R54  ValueDisplayed: 1.50k  [0402]  (hidden comment: RMCF0402FT1K50)
R55  ValueDisplayed: 470  [0402]  (hidden comment: CRCW0402470RJNED)
R56  ValueDisplayed: 1.50k  [0402]  (hidden comment: RMCF0402FT1K50)
R57  ValueDisplayed: 470  [0402]  (hidden comment: CRCW0402470RJNED)
R58  ValueDisplayed: 470  [0402]  (hidden comment: CRCW0402470RJNED)
R59  ValueDisplayed: 1.50k  [0402]  (hidden comment: RMCF0402FT1K50)
R60  ValueDisplayed: 1.50k  [0402]  (hidden comment: RMCF0402FT1K50)
R78  ValueDisplayed: 0  [0201]  (hidden comment: CRCW02010000Z0ED)
R88  ValueDisplayed: 0  [0603]  (hidden comment: CRCW06030000Z0EA)
R96  ValueDisplayed: 0  [0201]  (hidden comment: CRCW02010000Z0ED)
R97  ValueDisplayed: 0  [0201]  (hidden comment: CRCW02010000Z0ED)
R98  ValueDisplayed: 0  [0201]  (hidden comment: CRCW02010000Z0ED)
R99  ValueDisplayed: 0  [0201]  (hidden comment: CRCW02010000Z0ED)
R100  ValueDisplayed: 0  [0201]  (hidden comment: CRCW02010000Z0ED)
R101  ValueDisplayed: 0  [0201]  (hidden comment: CRCW02010000Z0ED)
R102  ValueDisplayed: 0  [0201]  (hidden comment: CRCW02010000Z0ED)
R103  ValueDisplayed: 0  [0201]  (hidden comment: CRCW02010000Z0ED)
R104  ValueDisplayed: 0  [0201]  (hidden comment: CRCW02010000Z0ED)
R105  ValueDisplayed: 2.2k  [0201M]  (hidden comment: CRCW02012K20JNED)
R107  ValueDisplayed: 0  [0201]  (hidden comment: CRCW02010000Z0ED)
R108  ValueDisplayed: 0  [0201]  (hidden comment: CRCW02010000Z0ED)
R111  5113  [FP-5113_0402-MFG]  (value not drawn)
R112  5113  [FP-5113_0402-MFG]  (value not drawn)
R113  5113  [FP-5113_0402-MFG]  (value not drawn)
R114  ValueDisplayed: 2.49k  [0402]  (hidden comment: CRCW04022K49FKED)
R115  ValueDisplayed: 1.50k  [0402]  (hidden comment: RMCF0402FT1K50)
S3  KSR221GLFS  [KSR]  (value not drawn)
T2  HX1188FNLT  [Pulse_HX1188FNLT]  (value not drawn)
U13  TPD4E05U06DQAR  [DQA0010A]
U14  DP83826A  [RHB0032M-MFG]
XTAL1  ECS-250-12-33Q-JES-TR  [ECS_ECS-33Q]  (value not drawn)

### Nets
EARTH_GND: C58.2 C59.2 C61.2 C63.2 J17.9 J17.10 J17.11 J17.12 J24.1 R51.1
GND: C43.2 C44.2 C45.2 C46.2 C47.2 C48.2 C49.2 C50.2 C51.2 C52.2 C53.2 C54.2 C55.2 C56.2 C57.2 C60.2 C61.1 C62.2 C63.1 C89.2 C92.2 C93.2 C94.2 C95.2 C96.2 C97.2 C98.2 J16.2 J16.3 J16.4 J16.5 J18.1 J18.3 J18.5 J18.6 J18.7 J18.9 J18.11 J18.12 J18.13 J18.15 J18.19 J18.21 J18.23 J18.25 J18.27 J18.28 J18.29 J18.31 J18.34 J18.35 J18.37 J18.38 J18.39 J18.41 J18.43 J18.45 J18.47 J18.48 J18.49 J18.51 J18.52 J18.58 J18.MP1 J18.MP2 J18.MP3 J18.MP4 LD3.2(K) LD4.2(K) LD5.2(K) LD6.2(K) R48.1 R49.1 R50.1 R51.2 R54.1 R56.2 R59.1 R60.1 R115.1 U13.3(GND) U13.8(GND) U14.33(Thermal_Pad) XTAL1.2(GND) XTAL1.4(GND)
VDDA3P3: R41.2
VDDIO: C88.2 J18.2 J18.4 R47.2 R88.1 R105.2 R114.1
BC1: C58.1 R43.1 R44.1  [also labelled BC2]
BC3: C59.1 R45.1 R46.1
C1: R44.2 T2.15(CMT)
C2: R43.2 T2.10(CMT)
CLK_OUT: R57.1 R59.2 R108.1 U14.31(CLKOUT/LED1/Strap1)
CLK_OUT_S: J18.54 R108.2
COL: R53.1 R56.1 R97.1 U14.28(COL/LED2/TX_ER/GPIO/Strap4)
COL_S: J18.18 R97.2
CRS: R58.1 R60.2 R96.1 U14.29(CRS/LED3/Strap3)
CRS_S: J18.16 R96.2
EXT_REF_CLK: J16.1 R42.1
LED_0: R54.2 R55.1 U14.30(LED0/Strap2)
MDC: R18.1 U14.12(MDC)
MDC_S: J18.8 R18.2
MDIO: R19.1 R47.1 U14.11(MDIO)
MDIO_S: J18.10 R19.2
PWDN: J18.55 U14.21(PWRDN/INT)
RBIAS: R48.2 U14.10(RBIAS)
RD_N: C97.1 R113.1 U14.4(RD_M)
RD_N1: C98.1 R113.2 T2.8(RD-) U13.5(D2-) U13.6(NC)
RD_P: C95.1 R112.1 U14.5(RD_P)
RD_P1: C96.1 R112.2 T2.6(RD+) U13.4(D2+) U13.7(NC)
RESET: C60.1 C88.1 J18.60 S3.2 U14.32(~{RST})
RX_CLK: J18.30 R104.2 R114.2 R115.2
RX_D0: J18.26 R78.2
RX_D1: J18.24 R102.2
RX_D2: J18.22 R101.2
RX_D3: J18.20 R100.2
RX_DV: J18.32 R103.2
RX_ER: J18.56 R99.2
TD_CH1_N: J17.2 T2.14(TX-)
TD_CH1_P: J17.1 T2.16(TX+)
TD_CH2_N: J17.6 T2.9(RX-)
TD_CH2_P: J17.3 T2.11(RX+)
TD_N: C93.1 R111.1 U14.6(TD_M)
TD_N1: C94.1 R111.2 T2.3(TD-) U13.2(D1-) U13.9(NC)
TD_P: C89.1 R52.1 U14.7(TD_P)
TD_P1: C92.1 R52.2 T2.1(TD+) U13.1(D1+) U13.10(NC)
TX_CLK: J18.36 R98.2
TX_D0: J18.46 U14.24(TX_D0)
TX_D1: J18.44 U14.25(TX_D1)
TX_D2: J18.42 U14.26(TX_D2)
TX_D3: J18.40 U14.27(TX_D3)
TX_EN: J18.50 U14.23(TX_EN)
XI: R40.1 R42.2 R107.1 U14.9(XI/50MHzIn)
XI_C: C44.1 R39.1 R40.2 XTAL1.1
XI_S: J18.14 R107.2
XO: R37.2 U14.8(XO)
NetC43_1: C43.1 R37.1 R39.2 XTAL1.3
NetC45_1: C45.1 C46.1 T2.2(TCT)
NetC47_1: C47.1 C48.1 C51.1 C52.1 R41.1 U14.3(VDDA3V3)
NetC49_1: C49.1 C50.1 C53.1 C54.1 R88.2 U14.17(VDDIO)
NetC55_1: C55.1 C56.1 T2.7(RCT)
NetC57_1: C57.1 C62.1 U14.2(CEXT)
NetJ17_4: J17.4 J17.5 R45.2
NetJ17_7: J17.7 J17.8 R46.2
NetLD3_1: LD3.1(A) R53.2
NetLD4_1: LD4.1(A) R55.2
NetLD5_1: LD5.1(A) R57.2
NetLD6_1: LD6.1(A) R58.2
NetR49_2: R49.2 S3.1
NetR50_2: R50.2 R105.1 U14.1(ModeSelect)
NetR78_1: R78.1 U14.16(Strap0/RX_D0)
NetR98_1: R98.1 U14.22(TX_CLK/Strap5)
NetR99_1: R99.1 U14.20(RX_ER/Strap6)
NetR100_1: R100.1 U14.13(Strap7/RX_D3)
NetR101_1: R101.1 U14.14(Strap8/RX_D2)
NetR102_1: R102.1 U14.15(Strap9/RX_D1)
NetR103_1: R103.1 U14.18(RX_DV/CRS_DV/Strap10)
NetR104_1: R104.1 U14.19(RX_CLK/50MHz_RMII/Strap11)

Not connected (* = marked no-connect by the designer): J18 17* 33* 53* 57* 59*; T2 4(NC)* 5(NC)* 12(NC)* 13(NC)*

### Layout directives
differential pair: RD_N, RD_N1, RD_P, RD_P1, TD_CH1_N, TD_CH1_P, TD_CH2_N, TD_CH2_P, TD_N, TD_N1, TD_P, TD_P1

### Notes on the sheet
- - VDDIO path gives this option on breakout connector
- Ferrite bead can replace 0 ohm resistors R41 and R88
- - DP83826A adds RX_CLK strap options
- (near R48) RBIAS 1% Tolerance
- - May need to reduce dielectric thickness between GND and MII signal layers
- - May need to increase dielectric thickness between Power and MII signal layers
- LED_2
- LED_1
- LED_3

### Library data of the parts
C43 C44 = CMP-0007071-4: CAP, CERM, 22 pF, 50 V, +/- 5%, C0G/NP0, AEC-Q200 Grade 1, 0603; Manufacturer: TDK; Polarized: N; Value: 22pF; U/M: EA; Value1: Unknown; VDC_V: 50V; TaMin_C: -55°C; TaMax_C: 125°C; SizeArea_mm2: 1.28; SizeAreaWB_mm2: 4.68; SizeX_mm: 1.6; SizeY_mm: 0.8; SizeZ_mm: 1; AEC Category: Q200; AEC Qualified: Y
C45 C55 = CMP-0006862-5: CAP, CERM, 0.1 uF, 10 V, +/- 10%, X7R, 0603; Manufacturer: Kemet; TaMin_C: -55°C; Polarized: N; SizeAreaWB_mm2: 4.68; Value1: Unknown; U/M: EA; Value: 0.1uF; TaMax_C: 125°C; SizeZ_mm: 1; SizeX_mm: 1.6; SizeY_mm: 0.8; Value2: 10V; SizeArea_mm2: 1.28; Cap_F: 100nF; AEC Category: Q200
C46 C56 = CMP-0007195-4: CAP, CERM, 2000 pF, 50 V, +/- 5%, C0G/NP0, 0603; Manufacturer: MuRata; TaMin_C: -55°C; Polarized: N; SizeAreaWB_mm2: 4.68; Value1: Unknown; U/M: EA; Value: 2000pF; TaMax_C: 125°C; SizeZ_mm: 1; SizeX_mm: 1.6; SizeY_mm: 0.8; SizeArea_mm2: 1.28; Cap_F: 2nF; AEC Category: Q200
C47 C49 C57 C62 = CMP-0078241-1: CAP, CERM, 0.1 µF, 10 V,+/- 10%, X7R, 0402; Manufacturer: Kemet; Polarized: N; Value: 0.1uF; U/M: EA; Cap_F: 100nF; VDC_V: 10V; TaMin_C: -55°C; TaMax_C: 125°C; AEC Category: Q200; SizeArea_mm2: 0.5; SizeAreaWB_mm2: 3; SizeX_mm: 1; SizeZ_mm: 0.6
C48 C50 = CMP-0006340-2: CAP, CERM, 10 uF, 6.3 V, +/- 20%, X5R, 0402; Manufacturer: Samsung Electro-Mechanics; TaMin_C: -55°C; Polarized: N; SizeAreaWB_mm2: 3; Value1: Unknown; U/M: EA; Value: 10uF; TaMax_C: 85°C; SizeZ_mm: 0.6; SizeX_mm: 1; SizeY_mm: 0.5; Value2: 6.3V; Cap_F: 10µF; AEC Category: Q200
C51 C53 C60 = CMP-0006227-2: CAP, CERM, 0.01 uF, 16 V, +/- 10%, X7R, 0402; Manufacturer: Wurth Elektronik; TaMin_C: -55°C; Polarized: N; SizeAreaWB_mm2: 3; Value1: Unknown; U/M: EA; Value: 0.01uF; TaMax_C: 125°C; SizeZ_mm: 0.6; SizeX_mm: 1; SizeY_mm: 0.5; Value2: 16V; Cap_F: 10nF; AEC Category: Q200
C52 C54 = CMP-0064947-2: CAP, CERM, 1 uF, 6.3 V,+/- 10%, X7R, 0402; Manufacturer: MuRata; TaMin_C: -55°C; Polarized: N; SizeAreaWB_mm2: 3; Value1: Unknown; U/M: EA; Value: 1uF; TaMax_C: 125°C; SizeZ_mm: 0.6; SizeX_mm: 1; SizeY_mm: 0.5; Cap_F: 1µF; AEC Category: Q200
C58 C59 = CMP-0008579-2: CAP, CERM, 1000 pF, 2000 V, +/- 10%, X7R, AEC-Q200 Grade 1, 1206; Manufacturer: Kemet; TaMin_C: -55°C; Polarized: N; SizeAreaWB_mm2: 10.92; Value1: Unknown; U/M: EA; Value: 1000pF; TaMax_C: 125°C; SizeZ_mm: 1.8; SizeX_mm: 3.2; SizeY_mm: 1.6; Cap_Case: 1206; Value2: 2000V; SizeArea_mm2: 5.12; AEC Qualified: Y; Cap_F: 1nF; VDC_V: 2kV; AEC Grade: 1; AEC Category: Q200
C61 C63 = CMP-0009295-2: CAP, CERM, 4700 pF, 2000 V, +/- 10%, X7R, 1812; Manufacturer: AVX; Polarized: N; Value: 4700pF; U/M: EA; Cap_F: 4.7nF; Value1: Unknown; VDC_V: 2kV; Value2: 2000V; TaMin_C: -55°C; TaMax_C: 125°C; Cap_Case: 1812; AEC Category: Q200; SizeArea_mm2: 14.4; SizeAreaWB_mm2: 23.1; SizeX_mm: 4.5; SizeY_mm: 3.2; SizeZ_mm: 2.54
C88 = CMP-0093676-1: Chip Multilayer Ceramic Capacitors for General Purpose, 0402, 2.2uF, X7R, 15%, 10%, 10V; Manufacturer: Murata; Value: 2.2µF; SizeZ_mm: 0.65mm; AEC Qualified: No
C89 C92-C98 = CMP-0009653-3: CAP, CERM, 330 pF, 50 V, +/- 10%, X7R, AEC-Q200 Grade 1, 0201; Manufacturer: TDK; TaMin_C: -55°C; ESR_ohm: 8.053; Polarized: N; SizeAreaWB_mm2: 2.08; Value1: 8.05302 ohm; U/M: EA; Value: 330pF; TaMax_C: 125°C; SizeZ_mm: 0.33; SizeX_mm: 0.6; SizeY_mm: 0.3; SizeArea_mm2: 0.18; AEC Qualified: Y; IRMS_A: 210.618mA; AEC Grade: 1; AEC Category: Q200
J16 = CMP-0054990-1: SMA Straight PCB Socket Die Cast, 50 Ohm, TH; Manufacturer: TE Connectivity; CNHeader: FALSE; Green_Lifecycle: Active; Green_REACh: Passed; CT: TRUE
J17 = CMP-0054918-1: RJ45, No LED, tab up, R/A, TH; Manufacturer: TE Connectivity; CNHeader: FALSE; Green_Lifecycle: Active; Green_REACh: Passed; ContactFinish: Gold; CT: TRUE
J18 = CMP-0055720-1: Receptacle, 0.8mm, 30x2, Gold, Edge Mount; Manufacturer: Samtec; CNHeader: FALSE; Current_A: 2.2A; Gender: Female; Voltage_V: 200V; CompType: Card Edge Socket; Row_Count: 2; Pitch_mm: 0.8; CT: TRUE; Cert_UL: Y
J24 = CMP-0055113-1: as J4 on sheet HSDC203A_Power
LD3-LD6 = CMP-0002917-2: as LD1 on sheet HSDC203A_Power
R18 R19 R37 R40 R42 R78 R96-R104 R107 R108 = CMP-0027008-4: RES, 0, 5%, 0.05 W, 0201; Manufacturer: Vishay-Dale; Power_W: 50mW; TempCo: ppm/C; Value_Code: 0000; Value: 0; EIA_Code: E24; SizeX_mm: 0.6; SizeY_mm: 0.3; SizeZ_mm: 0.26; Value2: 0.05W; SizeArea_mm2: 0.18; AEC Qualified: N; AEC Category: Q200
R39 = CMP-0026727-1: RES, 1.00 M, 1%, 0.063 W, 0402; Manufacturer: Yageo America; Value: 1.00Meg; Res_ohm: 1M; Value_Code: 1M00; Power_W: 63mW; Value2: 0.063W; TempCo: 100 ppm/C; EIA_Code: E96; U/M: EA; AEC Category: Q200; SizeArea_mm2: 0.5; SizeX_mm: 1; SizeZ_mm: 0.6
R41 R88 = CMP-0025697-4: RES, 0, 5%, 0.1 W, AEC-Q200 Grade 0, 0603; Manufacturer: Vishay-Dale; Power_W: 100mW; TempCo: 200 ppm/C; Value_Code: 0000; Value: 0; EIA_Code: E24; SizeX_mm: 1.6; SizeY_mm: 0.8; SizeZ_mm: 1; Value2: 0.1W; SizeArea_mm2: 1.28; AEC Qualified: Y; VDC_V: 75V; AEC Category: Q200
R43-R46 = CMP-0021425-3: RES, 75.0, 1%, 0.125 W, AEC-Q200 Grade 0, 0805; Manufacturer: Vishay-Dale; Power_W: 125mW; TempCo: 100 ppm/C; Value_Code: 75R0; Value: 75.0; EIA_Code: E96; Res_ohm: 75; SizeX_mm: 2; SizeY_mm: 1.25; SizeZ_mm: 1.45; Value2: 0.125W; SizeArea_mm2: 2.5; AEC Qualified: Y; VDC_V: 150V; AEC Category: Q200; AEC Grade: 0
R47 = CMP-0026890-5: RES, 2.2 k, 5%, 0.063 W, AEC-Q200 Grade 0, 0402; Manufacturer: Vishay-Dale; Power_W: 63mW; TempCo: 200 ppm/C; Value_Code: 2k20; Value: 2.2k; EIA_Code: E24; SizeX_mm: 1; SizeY_mm: 0.5; SizeZ_mm: 0.6; Value2: 0.063W; AEC Qualified: Y; VDC_V: 50V; AEC Category: Q200; AEC Grade: 0
R48 = CMP-0026515-2: RES, 6.49 k, 1%, 0.063 W, AEC-Q200 Grade 0, 0402; Manufacturer: Vishay-Dale; Power_W: 63mW; TempCo: 100 ppm/C; Value_Code: 6k49; Value: 6.49k; EIA_Code: E96; SizeX_mm: 1; SizeY_mm: 0.5; SizeZ_mm: 0.6; Value2: 0.063W; CompType: Resistor; AEC Qualified: Y; VDC_V: 50V; AEC Category: Q200; AEC Grade: 0
R49 = CMP-0027127-1: RES, 470, 5%, 0.05 W, 0201; Manufacturer: Yageo America; Power_W: 50mW; TempCo: 200 ppm/C; Value_Code: 470R; U/M: EA; Value: 470; EIA_Code: E24; SizeX_mm: 0.6; SizeY_mm: 0.3; SizeZ_mm: 0.26; Value2: 0.05W; SizeArea_mm2: 0.18; AEC Qualified: N; VDC_V: 25V; AEC Category: Q200
R50 = CMP-0065361-1: RES, 0, 5%, .05 W, AEC-Q200 Grade 0, 0201; Manufacturer: Panasonic; Power_W: 50mW; Green_Lifecycle: Not Set; TempCo: ppm/C; Value_Code: 0000; Green_REACh: Incomplete; U/M: EA; Value: 0; EIA_Code: E24; SizeX_mm: 0.6; SizeY_mm: 0.3; SizeZ_mm: 0.26; Value2: .05W; SizeArea_mm2: 0.18; AEC Qualified: Y; AEC Category: Q200
R51 = CMP-0016200-2: RES, 10 M, 5%, 0.5 W, 2010; Manufacturer: TT Electronics/IRC; Power_W: 500mW; TempCo: 100 ppm/C; Value_Code: 10M0; U/M: EA; Value: 10Meg; EIA_Code: E24; SizeX_mm: 5; SizeY_mm: 2.5; SizeZ_mm: 1.66; Value2: 0.5W; SizeArea_mm2: 12.5; AEC Qualified: N; VDC_V: 2kV; AEC Category: Q200
R52 R111-R113 = CMP-0120020-1: 0 Ohms Jumper Chip Resistor 0402 (1005 Metric) Metal Element; Manufacturer: Keystone Electronics; AEC Qualified: No; Res_ohm: 0; SizeZ_mm: 0.63mm; Value: 0
R53 R55 R57 R58 = CMP-0026934-3: as R29 on sheet HSDC203A_Power
R54 R56 R59 R60 R115 = CMP-0026756-1: RES, 1.50 k, 1%, 0.063 W, AEC-Q200 Grade 0, 0402; Manufacturer: Stackpole Electronics Inc; Power_W: 63mW; TempCo: 100 ppm/C; Value_Code: 1k50; U/M: EA; Value: 1.50k; EIA_Code: E96; Res_ohm: 1.5k; SizeX_mm: 1; SizeY_mm: 0.5; SizeZ_mm: 0.6; Value2: 0.063W; AEC Qualified: Y; VDC_V: 50V; AEC Grade: 0; AEC Category: Q200
R105 = CMP-0027010-2: RES, 2.2 k, 5%, 0.05 W, 0201; Manufacturer: Vishay-Dale; Value: 2.2k; Value_Code: 2k20; Power_W: 50mW; Value2: 0.05W; VDC_V: 30V; TempCo: 200 ppm/C; EIA_Code: E24; AEC Category: Q200; AEC Qualified: N; SizeArea_mm2: 0.18; SizeX_mm: 0.6; SizeY_mm: 0.3; SizeZ_mm: 0.26
R114 = CMP-0026237-2: RES, 2.49 k, 1%, 0.063 W, AEC-Q200 Grade 0, 0402; Manufacturer: Vishay-Dale; Power_W: 63mW; TempCo: 100 ppm/C; Value_Code: 2k49; Value: 2.49k; EIA_Code: E96; SizeX_mm: 1; SizeY_mm: 0.5; SizeZ_mm: 0.6; Value2: 0.063W; AEC Qualified: Y; VDC_V: 50V; AEC Grade: 0; AEC Category: Q200
S3 = CMP-0002170-2: Switch, Normally open, 2.3N force, 200k operations, SMD; Manufacturer: C&K Components; Circuit: SPST Switch; VDC_V: 32V; SwitchFunction: Off-Mom; PositionCount: 1; CurrentRating_mA: 1.001kA
T2 = CMP-0030425-2: Transformer, 350 uH, SMT; Manufacturer: Pulse Engineering; Green_Lifecycle: Not Set; Green_REACh: Incomplete; Value: 350uH; Lp: 350; Ind_H: 350µH
U13 = CMP-0073613-3: 4-Channel Ultra-Low-Capacitance IEC ESD Protection Diode, DQA0010A (USON-10); Alternate Manufacturer: Texas Instruments; Green_Lifecycle: Active; SizeAreaWB_mm2: 7.0; Green_REACh: Passed; SizeZ_mm: 0.55; SizeX_mm: 1.0; SizeY_mm: 2.5; CompType: IC; AEC Category: Q200; AEC Qualified: N
U14 = CMP-0124715-1: Deterministic, Low-Latency, Low-Power, 10/100 Mbps, Industrial Ethernet PHY; Manufacturer: Texas Instruments; SizeZ_mm: 1mm; AEC Qualified: No; Data Rate: 100Mbits/s; Interface: Ethernet,Other; Max Supply Voltage: 3.6V; Min Supply Voltage: 1.62V; Number Of Channels: 1; Simplex Duplex: Full-Duplex; Standoff Height: 0mm; TaMax_C: +85°C; TaMin_C: -40°C
XTAL1 = CMP-0079863-1: Crystal, 25 MHz, 20 ppm, AEC-Q200 Grade 1, SMD; Manufacturer: ECS Inc.; TaMin_C: -55°C; Frequency Tolerance: 20 ppm; Frequency Stability: 50 ppm; SizeAreaWB_mm2: 14.7; Frequency_Fixed: 25MHz; TaMax_C: 125°C; SizeZ_mm: 0.8; SizeX_mm: 2.5; SizeY_mm: 3.2; SizeArea_mm2: 8; AEC Qualified: Y; AEC Grade: 1; AEC Category: Q200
